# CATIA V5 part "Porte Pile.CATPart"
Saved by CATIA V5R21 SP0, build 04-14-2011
Part number: Porte piles
Bounding box of the stored display mesh (mm): x -7 to 20, y 0 to 105, z 0 to 69
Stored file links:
  C:\Users\2027.DESARCY-LEMIE30\Desktop\Assemblage26.05\Porte Pile.CATPart
  D:\carte arduino.CATPart
  C:\Users\2027.DESARCY-LEMIE30\Desktop\V16(05.04.2023)\Fixation carte arduino v3.CATPart
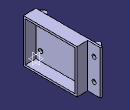
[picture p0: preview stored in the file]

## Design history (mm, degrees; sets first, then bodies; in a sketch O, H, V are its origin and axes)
Body1 (main body)
  Sketch1 on yz-plane, origin (0, 0, 0), H (0, 1, 0), V (0, 0, 1)
    line L1 (0, 0) -> (105, 0)
    line L2 (105, 0) -> (105, 69)
    line L3 (105, 69) -> (0, 69)
    line L4 (0, 69) -> (0, 0)
    length L3 = 105
    length L2 = 69
    horizontal: L1 H, L3 H
    vertical: L2 V, L4 V
  Pad1: profile Sketch1, direction (1, 0, 0), length 3
  Sketch2 on end face of Pad1, origin (3, 0, 0), H (0, 1, 0), V (0, 0, 1)
    line L1 (0, 69) -> (85, 69)
    line L2 (85, 69) -> (85, 0)
    line L3 (85, 0) -> (0, 0)
    line L4 (0, 0) -> (0, 69)
    point P4 (0, 0)
    reference projected line E1 (110, 69) -> (0, 69) from edge [face of Pad1 from Sketch1.L3 | end face of Pad1]
    reference projected line E2 (0, 0) -> (105, 0) from edge [face of Pad1 from Sketch1.L1 | end face of Pad1]
    line L5 (3, 66) -> (82, 66)
    line L6 (82, 66) -> (82, 3)
    line L7 (82, 3) -> (3, 3)
    line L8 (3, 3) -> (3, 66)
    distance L5 L1 = 3
    distance L7 L3 = 3
    distance L6 L2 = 3
    distance L8 L4 = 3
    distance L8 L6 = 79
    horizontal: L1 H, L3 H, L5 H, L7 H
    vertical: L2 V, L4 V, L6 V, L8 V
    coincidence: L1 E1, L3 E2, O P4
  Pad2: profile Sketch2, direction (1, 0, 0), length 17
  Sketch3 on face of Pad2, origin (0, 0, 0), H (1, 0, 0), V (0, -1, 0)
    construction line L1 (-26.9072, -52.5) -> (75.9513, -52.5)
    reference projected line E1 (0, -105) -> (3, -105) from edge [face of Pad1 from Sketch1.L2 | face of Pad1 from Sketch1.L1]
    axis line L2 (-22.3256, -9.9) -> (35.4035, -9.9)
    point P5 (0, -6.9)
    line L3 (0, -6.9) -> (-2.1, -6.9)
    point P6 (-2.1, -6.9)
    line L4 (-2.1, -6.9) -> (-2.1, -3.1)
    point P7 (-2.1, -3.1)
    line L5 (-2.1, -3.1) -> (-7, -8)
    point P8 (-7, -8)
    line L6 (-7, -8) -> (-7, -9.9)
    point P9 (-7, -9.9)
    point P10 (0, -9.9)
    line L7 (0, -9.9) -> (0, -6.9)
    reference projected line E2 (0, 0) -> (0, -105) from edge [start face of Pad1 | face of Pad1 from Sketch1.L1]
    point P11 (0, -12.9)
    point P12 (-2.1, -12.9)
    point P13 (-2.1, -16.7)
    point P14 (-7, -11.8)
    point P15 (-7, -9.9)
    point P16 (0, -9.9)
    line L8 (0, -12.9) -> (-2.1, -12.9)
    line L9 (-2.1, -12.9) -> (-2.1, -16.7)
    line L10 (-2.1, -16.7) -> (-7, -11.8)
    line L11 (-7, -11.8) -> (-7, -9.9)
    line L12 (0, -9.9) -> (0, -12.9)
    point P17 (0, -98.1)
    point P18 (-2.1, -98.1)
    point P19 (-2.1, -101.9)
    point P20 (-7, -97)
    point P21 (-7, -95.1)
    point P22 (0, -95.1)
    point P23 (0, -92.1)
    point P24 (-2.1, -92.1)
    point P25 (-2.1, -88.3)
    point P26 (-7, -93.2)
    point P27 (-7, -95.1)
    point P28 (0, -95.1)
    line L13 (0, -98.1) -> (-2.1, -98.1)
    line L14 (-2.1, -98.1) -> (-2.1, -101.9)
    line L15 (-2.1, -101.9) -> (-7, -97)
    line L16 (-7, -97) -> (-7, -95.1)
    line L17 (0, -95.1) -> (0, -98.1)
    line L18 (0, -92.1) -> (-2.1, -92.1)
    line L19 (-2.1, -92.1) -> (-2.1, -88.3)
    line L20 (-2.1, -88.3) -> (-7, -93.2)
    line L21 (-7, -93.2) -> (-7, -95.1)
    line L22 (0, -95.1) -> (0, -92.1)
    reference projected line E3 (0, 0) -> (3, 0) from edge [face of Pad2 | face of Pad2]
    distance E1 L1 = 52.5
    length L7 = 3
    length L4 = 3.8
    angle L5 L4 = 45
    length L6 = 1.9
    distance L6 L7 = 7
    distance L3 E3 = 6.9
    horizontal: L1 H, L2 H, L3 H
    vertical: L4 V, L6 V, L7 V
    coincidence: P9 L2, P10 L2, L7 E2, P9 P15, P10 P16, P21 P27, P22 P28
    symmetry: P5 P11 L2, P6 P12 L2, P7 P13 L2, P8 P14 L2, P9 P15 L2, P10 P16 L2, L3 L8 L2, L4 L9 L2, L5 L10 L2, L6 L11 L2, L7 L12 L2, P5 P17 L1, P6 P18 L1, P7 P19 L1, P8 P20 L1, P9 P21 L1, P10 P22 L1, P11 P23 L1, P12 P24 L1, P13 P25 L1, P14 P26 L1, P15 P27 L1, P16 P28 L1, L3 L13 L1, L4 L14 L1, L5 L15 L1, L6 L16 L1, L7 L17 L1, L8 L18 L1, L9 L19 L1, L10 L20 L1, L11 L21 L1, L12 L22 L1
  Pad3: profile Sketch3, direction (0, 0, 1), length 67
  Sketch4 on end face of Pad1, origin (3, 16.9157, 27.9903), H (0, 1, 0), V (0, 0, 1)
    point P1 (78.1843, 23.7597)
    construction line L1 (-16.9157, 6.5097) -> (88.0843, 6.5097)
    point P2 (-16.9157, 6.5097)
    point P3 (88.0843, 6.5097)
    reference projected line E1 (88.0843, -27.9903) -> (88.0843, 40.0097) from edge [face of Pad1 from Sketch1.L2 | end face of Pad1]
    reference projected line E2 (-16.9157, 41.0097) -> (-16.9157, -27.9903) from edge [face of Pad2 | end face of Pad2]
    construction line L2 (35.5843, 6.5097) -> (35.5843, 41.0097)
    point P4 (35.5843, 6.5097)
    point P5 (35.5843, 41.0097)
    reference projected line E3 (68.0843, 41.0097) -> (-16.9157, 41.0097) from edge [face of Pad3 | end face of Pad2]
    reference projected line E4 (93.0843, 41.0097) -> (-16.9157, 41.0097) from edge [face of Pad3 | end face of Pad1]
    reference projected line E5 (-16.9157, -27.9903) -> (88.0843, -27.9903) from edge [face of Pad3 | end face of Pad1]
    reference projected line E6 (93.0843, 41.0097) -> (-16.9157, 41.0097) from edge [face of Pad3 | end face of Pad1]
    construction line L3 (35.5843, 23.7597) -> (88.0843, 23.7597)
    point P6 (35.5843, 23.7597)
    point P7 (88.0843, 23.7597)
    reference projected line E7 (88.0843, -27.9903) -> (88.0843, 40.0097) from edge [face of Pad1 from Sketch1.L2 | end face of Pad1]
    axis line L4 (78.1843, 41.0097) -> (78.1843, -27.9903)
    point P8 (78.1843, 41.0097)
    point P9 (78.1843, -27.9903)
    reference projected line E8 (68.0843, 41.0097) -> (-16.9157, 41.0097) from edge [face of Pad3 | end face of Pad2]
    reference projected line E9 (-16.9157, -27.9903) -> (68.0843, -27.9903) from edge [face of Pad3 | end face of Pad2]
    reference projected line E10 (88.0843, -27.9903) -> (88.0843, 40.0097) from edge [face of Pad1 from Sketch1.L2 | end face of Pad1]
    distance E4 E5 = 69 (reference)
    distance L1 E6 = 34.5
    distance L4 E10 = 9.9
    horizontal: L1 H, L3 H
    coincidence: P3 E1, P2 E2, P5 E3, P7 E7, E8 P8, P9 E9, P1 L4, P1 L3
    vertical: L2 V, L4 V
    midpoint: P4 L1, P6 L2
  Hole1: placed by Sketch4, at (3, 95.1, 51.75) direction (-1, 0, 0), diameter 3.8, depth 12, counterbore diameter 6.8, counterbore depth 4
  RectPattern1: of Hole1, direction 1 instances 2, spacing 84.7, along end face of Pad1 reversed, direction 2 instances 2, spacing -34.5, along end face of Pad1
